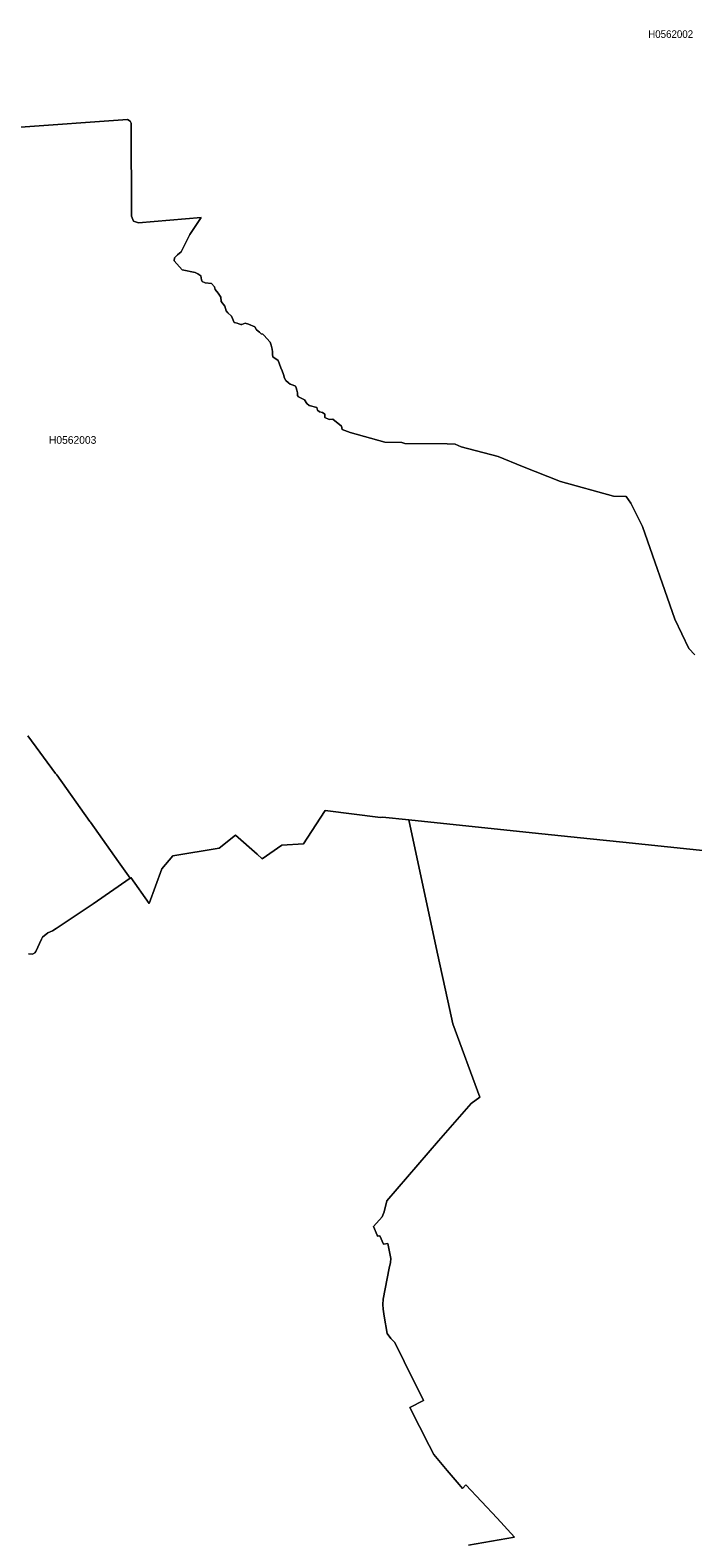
# Model space of a CAD drawing. Extents: x 369010 to 739155, y 6377141 to 6616555.
# Drawn here: x 493332 to 501969, y 6546276 to 6565934 of the extents above; entities that cross this region are included whole.
import ezdxf
from ezdxf.enums import TextEntityAlignment as Align

# ---------------------------------------------------------------- set-up
doc = ezdxf.new("R2010")
doc.units = 0
doc.header["$LTSCALE"] = 40
doc.layers.add('1', color=7, linetype='Continuous', lineweight=13)
doc.layers.add('2', color=7, linetype='Continuous')

msp = doc.modelspace()

# ---------------------------------------------------------------- linework, layer by layer
at = {"layer": '1'}
for points in [[(496816.53, 6561206.26), (496807.26, 6561239.69), (496796.84, 6561268.65), (496791.71, 6561290.5), (496758.27, 6561304.4), (496722.52, 6561316.48), (496699.35, 6561334.69), (496664.76, 6561366.3), (496646.06, 6561396.92), (496631.66, 6561444.09), (496616.27, 6561493.57), (496600.88, 6561530.32), (496563.14, 6561627.8), (496548.58, 6561640.71), (496526.57, 6561651.96), (496496.78, 6561675.63), (496490.98, 6561704.26), (496489.33, 6561740.01), (496485.85, 6561776.25), (496473.28, 6561825.74), (496458.71, 6561866.95), (496416.01, 6561914.78), (496381.42, 6561954.67), (496363.55, 6561969.07), (496341.04, 6561974.36), (496320.35, 6561998.53), (496280.96, 6562028.48), (496261.93, 6562068.2), (496179.01, 6562102.63), (496134.99, 6562115.54), (496090.63, 6562098.32), (496075.57, 6562096.5), (496052.56, 6562106.93), (496030.55, 6562115.54), (495989.01, 6562124.14), (495953.92, 6562203.92), (495906.59, 6562248.93), (495886.4, 6562273.1), (495869.02, 6562337.15), (495822.84, 6562394.74), (495818.21, 6562452.01), (495783.62, 6562503.31), (495745.06, 6562554.62), (495733.47, 6562588.05), (495695.9, 6562633.07), (495613.81, 6562640.35), (495573.93, 6562655.41), (495566.48, 6562679.08), (495555.56, 6562731.05), (495515.67, 6562759.18), (495481.08, 6562776.56), (495310.94, 6562810.65), (495207, 6562927.17), (495213.46, 6562964.08), (495251.36, 6563006.28), (495300.51, 6563044.84), (495413.55, 6563272.08), (495562.51, 6563492.37), (494744.42, 6563420.87), (494677.39, 6563443.87), (494652.57, 6563509.25), (494648.59, 6564719.91), (494635.85, 6564747.55), (494598.94, 6564769.56), (493146.31, 6564666.78)], [(493146.31, 6564666.78), (494598.94, 6564769.56), (494635.85, 6564747.55), (494648.59, 6564719.91), (494652.57, 6563509.25), (494677.39, 6563443.87), (494744.42, 6563420.87), (495562.51, 6563492.37), (495413.55, 6563272.08), (495300.51, 6563044.84), (495251.36, 6563006.28), (495213.46, 6562964.08), (495207, 6562927.17), (495310.94, 6562810.65)], [(495310.94, 6562810.65), (495481.08, 6562776.56), (495515.67, 6562759.18), (495555.56, 6562731.05), (495566.48, 6562679.08), (495573.93, 6562655.41), (495613.81, 6562640.35), (495695.9, 6562633.07), (495733.47, 6562588.05), (495745.06, 6562554.62), (495783.62, 6562503.31), (495818.21, 6562452.01), (495822.84, 6562394.74), (495869.02, 6562337.15), (495886.4, 6562273.1), (495906.59, 6562248.93), (495953.92, 6562203.92), (495989.01, 6562124.14), (496030.55, 6562115.54), (496052.56, 6562106.93), (496075.57, 6562096.5), (496090.63, 6562098.32), (496134.99, 6562115.54), (496179.01, 6562102.63), (496261.93, 6562068.2), (496280.96, 6562028.48), (496320.35, 6561998.53), (496341.04, 6561974.36), (496363.55, 6561969.07), (496381.42, 6561954.67), (496416.01, 6561914.78), (496458.71, 6561866.95), (496473.28, 6561825.74), (496485.85, 6561776.25), (496489.33, 6561740.01), (496490.98, 6561704.26), (496496.78, 6561675.63), (496526.57, 6561651.96), (496548.58, 6561640.71), (496563.14, 6561627.8), (496600.88, 6561530.32), (496616.27, 6561493.57), (496631.66, 6561444.09), (496646.06, 6561396.92), (496664.76, 6561366.3), (496699.35, 6561334.69), (496722.52, 6561316.48), (496758.27, 6561304.4), (496791.71, 6561290.5), (496796.84, 6561268.65), (496807.26, 6561239.69), (496816.53, 6561206.26), (496815.37, 6561169.35), (496828.12, 6561154.29), (496863.2, 6561135.92), (496908.22, 6561113.91), (496937.02, 6561067.23), (496969.46, 6561040.09), (497066.28, 6561016.43), (497077.36, 6560978.86), (497102.69, 6560957.51), (497140.75, 6560947.24), (497171.87, 6560927.05), (497170.71, 6560884.85), (497227.97, 6560856.05), (497277.46, 6560864.16), (497388.84, 6560769), (497397.62, 6560727.95), (497501.39, 6560689.89), (497954.7, 6560562.45), (498177.97, 6560558.31), (498213.22, 6560545.73), (498765.17, 6560540.44), (498870.77, 6560535.31), (498951.04, 6560499.56), (499431.99, 6560374.93), (499748.1, 6560245.84), (500244.28, 6560047.4), (500935.59, 6559856.9), (501099.44, 6559854.59), (501161.01, 6559768.86), (501315.09, 6559461.18), (501736.3, 6558253.34), (501918.52, 6557871.35), (501996.97, 6557788.27)], [(501996.97, 6557788.27), (501918.52, 6557871.35), (501736.3, 6558253.34), (501315.09, 6559461.18), (501161.01, 6559768.86), (501099.44, 6559854.59), (500935.59, 6559856.9), (500244.28, 6560047.4), (499748.1, 6560245.84), (499431.99, 6560374.93), (498951.04, 6560499.56), (498870.77, 6560535.31), (498765.17, 6560540.44), (498213.22, 6560545.73), (498177.97, 6560558.31), (497954.7, 6560562.45), (497501.39, 6560689.89), (497397.62, 6560727.95), (497388.84, 6560769), (497277.46, 6560864.16), (497227.97, 6560856.05), (497170.71, 6560884.85), (497171.87, 6560927.05), (497140.75, 6560947.24), (497102.69, 6560957.51), (497077.36, 6560978.86), (497066.28, 6561016.43), (496969.46, 6561040.09), (496937.02, 6561067.23), (496908.22, 6561113.91), (496863.2, 6561135.92), (496828.12, 6561154.29), (496815.37, 6561169.35), (496816.53, 6561206.26)], [(493301.39, 6556734.84), (493659.87, 6556242.79), (493678.24, 6556224.09), (494109.22, 6555615.37), (494118.15, 6555608.25), (494483.26, 6555089.4), (494634.53, 6554878.71), (494645.28, 6554886.16), (494881.29, 6554545.88), (495045.97, 6554999.03), (495191.28, 6555170.66), (495796.53, 6555267.31), (496006.39, 6555439.6), (496290.23, 6555192.51), (496356.26, 6555129.12), (496612.96, 6555308.69), (496894.81, 6555326.73), (497112.62, 6555658.07), (497177.33, 6555761.84), (497895.95, 6555667.01), (497924.41, 6555671.64), (498267.17, 6555636.39), (499875.54, 6555467.41), (500632.72, 6555389.45), (501057.41, 6555347.09), (501928.29, 6555255.4), (502428.27, 6555202.44)], [(493311.16, 6553890.49), (493362.46, 6553888.17), (493390.76, 6553906.04), (493407.31, 6553921.77), (493479.14, 6554080.98), (493493.21, 6554107.63), (493563.72, 6554162.9), (493620.81, 6554192.36), (493671.62, 6554221.33), (494151.92, 6554544.72), (494634.53, 6554878.71), (494483.26, 6555089.4), (494118.15, 6555608.25), (494109.22, 6555615.37), (493678.24, 6556224.09), (493659.87, 6556242.79), (493301.39, 6556734.84)], [(499045.54, 6546180.65), (499644.5, 6546285.25), (499420.24, 6546531.52), (499011.44, 6546967.62), (498967.09, 6546918.46), (498923.4, 6546973.58), (498766.33, 6547156.29), (498592.72, 6547363.34), (498530.82, 6547479.36), (498279.75, 6547973.72), (498458.83, 6548068.22), (498206.1, 6548574.66), (498084.62, 6548821.59), (498034.81, 6548875.88), (497983.33, 6548941.25), (497946.76, 6549168.16), (497932.86, 6549255.88), (497929.21, 6549317.44), (497934.34, 6549386.79), (498011.47, 6549793.43), (498030.5, 6549864.6), (498032.32, 6549919.38), (497994.92, 6550112.86), (497935.5, 6550105.24), (497891.31, 6550213.65), (497862.68, 6550209.01), (497852.92, 6550221.26), (497808.56, 6550337.11), (497919.95, 6550459.75), (497946.26, 6550525.29), (497978.87, 6550671.6), (498656.11, 6551452.94), (499080.13, 6551938.37), (499191.35, 6552020.95), (498841.47, 6552979.05), (498776.43, 6553276.13), (498638.23, 6553914.15), (498267.17, 6555636.39), (497924.41, 6555671.64), (497895.95, 6555667.01), (497177.33, 6555761.84), (497112.62, 6555658.07), (496894.81, 6555326.73), (496612.96, 6555308.69), (496356.26, 6555129.12), (496290.23, 6555192.51), (496006.39, 6555439.6), (495796.53, 6555267.31), (495191.28, 6555170.66), (495045.97, 6554999.03), (494881.29, 6554545.88), (494645.28, 6554886.16), (494634.53, 6554878.71)], [(498267.17, 6555636.39), (498638.23, 6553914.15), (498776.43, 6553276.13), (498841.47, 6552979.05), (499191.35, 6552020.95), (499080.13, 6551938.37), (498656.11, 6551452.94), (497978.87, 6550671.6), (497946.26, 6550525.29), (497919.95, 6550459.75), (497808.56, 6550337.11), (497852.92, 6550221.26), (497862.68, 6550209.01), (497891.31, 6550213.65), (497935.5, 6550105.24), (497994.92, 6550112.86), (498032.32, 6549919.38), (498030.5, 6549864.6), (498011.47, 6549793.43), (497934.34, 6549386.79), (497929.21, 6549317.44), (497932.86, 6549255.88), (497946.76, 6549168.16), (497983.33, 6548941.25), (498034.81, 6548875.88), (498084.62, 6548821.59), (498206.1, 6548574.66), (498458.83, 6548068.22), (498279.75, 6547973.72), (498530.82, 6547479.36), (498592.72, 6547363.34), (498766.33, 6547156.29), (498923.4, 6546973.58), (498967.09, 6546918.46), (499011.44, 6546967.62), (499420.24, 6546531.52), (499644.5, 6546285.25), (499045.54, 6546180.65)], [(502428.27, 6555202.44), (501928.29, 6555255.4), (501057.41, 6555347.09), (500632.72, 6555389.45), (499875.54, 6555467.41), (498267.17, 6555636.39)], [(494634.53, 6554878.71), (494151.92, 6554544.72), (493671.62, 6554221.33), (493620.81, 6554192.36), (493563.72, 6554162.9), (493493.21, 6554107.63), (493479.14, 6554080.98), (493407.31, 6553921.77), (493390.76, 6553906.04), (493362.46, 6553888.17), (493311.16, 6553890.49)]]:
    msp.add_lwpolyline(points, dxfattribs=at)

# ---------------------------------------------------------------- texts
at = {"layer": '2', "width": 0.95}
msp.add_text('H0562002', height=100, dxfattribs=at).set_placement((501680.18, 6565832.93), align=Align.CENTER)
at = {"layer": '2'}
msp.add_text('H0562003', height=100, dxfattribs=at).set_placement((493885.41, 6560541.21), align=Align.CENTER)

doc.saveas('drawing.dxf')
